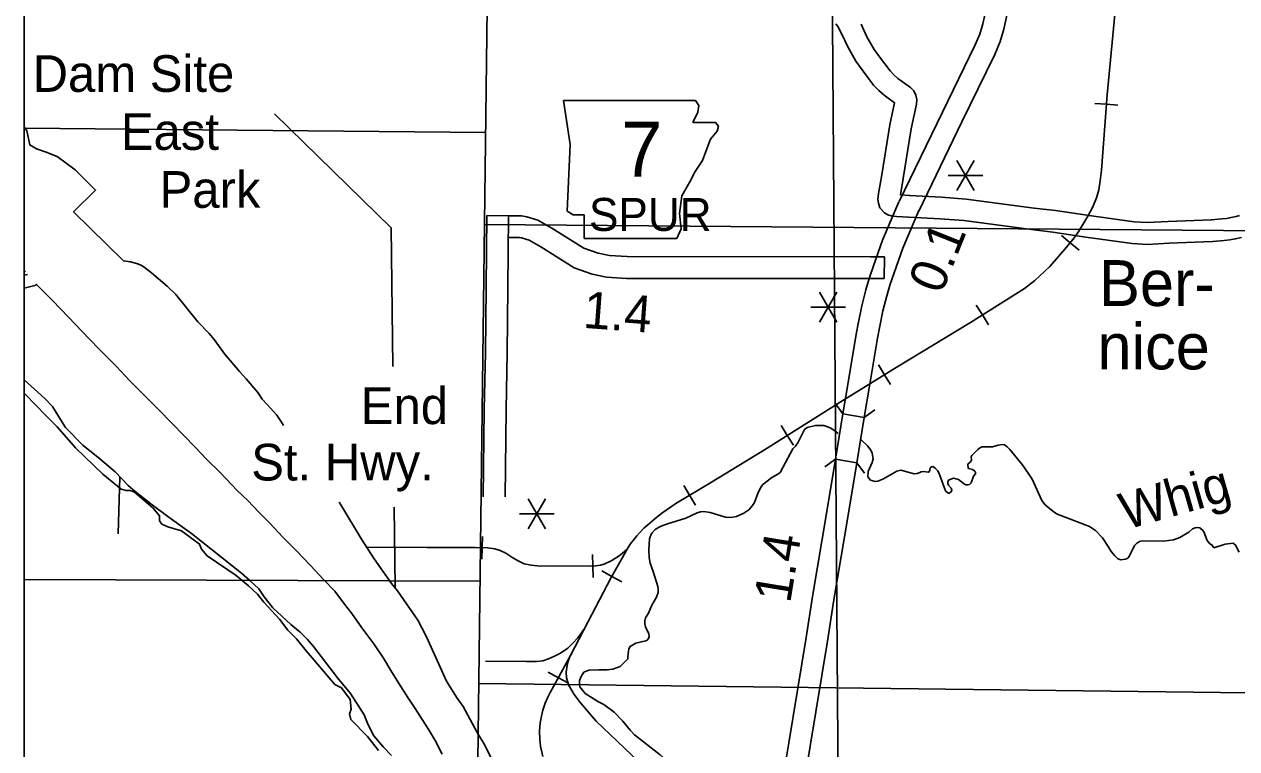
# Model space of a CAD drawing. Extents: x 1374139 to 1377472, y 1168351 to 1170484.
# Drawn here: x 1375090 to 1375369.3, y 1168970.5 to 1169137.4 of the extents above; entities that cross this region are included whole.
import ezdxf

# ---------------------------------------------------------------- set-up
doc = ezdxf.new("R2010")
doc.units = 0
doc.layers.add('26', color=7, linetype='Continuous')
doc.layers.add('Default', color=7, linetype='Continuous')

msp = doc.modelspace()

# ---------------------------------------------------------------- linework, layer by layer
at = {"layer": '26'}
msp.add_lwpolyline([(1375090, 1169579.43), (1376597.43, 1169579.43), (1376597.43, 1168653.79), (1375090, 1168653.79)], close=True, dxfattribs=at)
at = {"layer": 'Default'}
for p, q in [((1375214.22, 1169119.87), (1375215.75, 1169109.72)), ((1375245.35, 1169118.68), (1375244.65, 1169119.85)), ((1375245.18, 1169117.16), (1375245.35, 1169118.68)), ((1375339.26, 1169118.97), (1375336.63, 1169119.18)), ((1375339.26, 1169118.97), (1375341.89, 1169118.77)), ((1375244, 1169114.79), (1375245.18, 1169117.16)), ((1375249.24, 1169114.79), (1375244, 1169114.79)), ((1375248.06, 1169110.9), (1375249.58, 1169112.76)), ((1375249.92, 1169113.95), (1375249.24, 1169114.79)), ((1375249.58, 1169112.76), (1375249.92, 1169113.95)), ((1375215.75, 1169109.72), (1375215.07, 1169094.32)), ((1375247.21, 1169108.7), (1375248.06, 1169110.9)), ((1375246.2, 1169105.99), (1375247.21, 1169108.7)), ((1375244.51, 1169103.46), (1375246.2, 1169105.99)), ((1375308.78, 1169106.05), (1375304.78, 1169099.12)), ((1375304.78, 1169106.05), (1375308.78, 1169099.12)), ((1375243.32, 1169101.09), (1375244.51, 1169103.46)), ((1375302.78, 1169102.59), (1375310.78, 1169102.59)), ((1375241.46, 1169097.87), (1375243.32, 1169101.09)), ((1375240.95, 1169093.81), (1375241.46, 1169097.87)), ((1375201.53, 1169093.3), (1375196.53, 1169093.34)), ((1375215.07, 1169094.32), (1375216.42, 1169093.48)), ((1375216.42, 1169093.48), (1375218.96, 1169093.48)), ((1375218.96, 1169093.48), (1375218.96, 1169088.06)), ((1375241.29, 1169090.26), (1375240.95, 1169093.81)), ((1375196.04, 1169091.26), (1375468.4, 1169089.05)), ((1375240.28, 1169088.06), (1375241.29, 1169090.26)), ((1375218.96, 1169088.06), (1375240.28, 1169088.06)), ((1375330.93, 1169087.07), (1375328.89, 1169088.75)), ((1375330.93, 1169087.07), (1375332.96, 1169085.39)), ((1375288.08, 1169078.81), (1375288.14, 1169083.81)), ((1375090, 1169079.6), (1375090.75, 1169079.79)), ((1375090, 1169076.62), (1375092.76, 1169077.33)), ((1375277.19, 1169075.67), (1375273.19, 1169068.74)), ((1375273.19, 1169075.67), (1375277.19, 1169068.74)), ((1375271.19, 1169072.2), (1375279.19, 1169072.2)), ((1375310.7, 1169070.43), (1375309.29, 1169072.67)), ((1375310.7, 1169070.43), (1375312.11, 1169068.2)), ((1375288.17, 1169056.67), (1375286.78, 1169058.92)), ((1375288.17, 1169056.67), (1375289.56, 1169054.43)), ((1375278.57, 1169047.65), (1375283.5, 1169046.84)), ((1375265.76, 1169042.71), (1375264.36, 1169044.95)), ((1375265.76, 1169042.71), (1375267.17, 1169040.47)), ((1375276.85, 1169037.22), (1375281.78, 1169036.4)), ((1375243.26, 1169028.9), (1375241.9, 1169031.16)), ((1375243.26, 1169028.9), (1375244.63, 1169026.64)), ((1375210.08, 1169028.08), (1375206.08, 1169021.15)), ((1375206.08, 1169028.08), (1375210.08, 1169021.15)), ((1375204.09, 1169024.61), (1375212.08, 1169024.61)), ((1375195.49, 1169016.81), (1375195.58, 1169019.44)), ((1375195.49, 1169016.81), (1375195.41, 1169014.17)), ((1375220.97, 1169012.62), (1375220.92, 1169015.26)), ((1375220.97, 1169012.62), (1375221.02, 1169009.98)), ((1375225.37, 1169010.2), (1375223.06, 1169011.47)), ((1375225.37, 1169010.2), (1375227.68, 1169008.93)), ((1375213.03, 1168986.87), (1375210.71, 1168988.13)), ((1375213.03, 1168986.87), (1375215.35, 1168985.6))]:
    msp.add_line(p, q, dxfattribs=at)
for points in [[(1375192.44, 1168800.51), (1375199.95, 1169407.44)], [(1375274.18, 1169407.24), (1375277.97, 1168899.53)], [(1375303.96, 1169217.35), (1375303.54, 1169182.85), (1375303.59, 1169180.48), (1375303.86, 1169177.75), (1375304.21, 1169175.41), (1375305.24, 1169170.15), (1375307.93, 1169160.85), (1375310.54, 1169151.94), (1375311.12, 1169149.35), (1375311.5, 1169147.19), (1375311.7, 1169144.93), (1375311.72, 1169143.13), (1375311.53, 1169140.89), (1375310.82, 1169137.5), (1375310.09, 1169135.1), (1375308.99, 1169132.51), (1375301.47, 1169117.13), (1375291.53, 1169096.56)], [(1375296.03, 1169094.38), (1375305.97, 1169114.94), (1375313.53, 1169130.43), (1375314.8, 1169133.39), (1375315.66, 1169136.26), (1375316.49, 1169140.16), (1375316.72, 1169142.95), (1375316.69, 1169145.17), (1375316.47, 1169147.85), (1375316.02, 1169150.33), (1375315.39, 1169153.19), (1375312.73, 1169162.25), (1375310.11, 1169171.32), (1375309.14, 1169176.26), (1375308.83, 1169178.37), (1375308.59, 1169180.78), (1375308.54, 1169182.88), (1375308.96, 1169217.29)], [(1375334.98, 1169093.2), (1375336.12, 1169095.31), (1375337.01, 1169097.38), (1375337.54, 1169099.27), (1375337.85, 1169101.33), (1375338.1, 1169103.79), (1375339.43, 1169121.14), (1375341.48, 1169142.85)], [(1375334.98, 1169093.2), (1375336.12, 1169095.31), (1375337.01, 1169097.38), (1375337.54, 1169099.27), (1375337.85, 1169101.33), (1375338.1, 1169103.79), (1375339.43, 1169121.14), (1375341.48, 1169142.85)], [(1375278.25, 1169135.19), (1375277.45, 1169136.8), (1375276.96, 1169137.49)], [(1375293.65, 1169092.97), (1375290.91, 1169093.12), (1375289.71, 1169093.24), (1375288.88, 1169093.53), (1375288.11, 1169093.97), (1375287.06, 1169095.08), (1375286.73, 1169096.18), (1375286.62, 1169097.05), (1375286.78, 1169098.38), (1375287.5, 1169102.7), (1375289.38, 1169114.23), (1375290.47, 1169119.3), (1375288.04, 1169121.03), (1375286.81, 1169122.17), (1375285.65, 1169123.39), (1375283.2, 1169126.58), (1375281.52, 1169128.87), (1375279.67, 1169132.23), (1375278.24, 1169135.23)], [(1375282.75, 1169137.38), (1375284.11, 1169134.52), (1375285.74, 1169131.57), (1375287.2, 1169129.58), (1375289.45, 1169126.65), (1375290.33, 1169125.73), (1375291.21, 1169124.91), (1375294.13, 1169122.83), (1375294.9, 1169122.04), (1375295.38, 1169121.07), (1375295.56, 1169120.04), (1375295.52, 1169118.99), (1375294.29, 1169113.3), (1375292.43, 1169101.89), (1375291.8, 1169098.08), (1375293.91, 1169097.97)], [(1375214.22, 1169119.87), (1375244.65, 1169119.85)], [(1375174.89, 1169058.57), (1375174.55, 1169090.53), (1375147.64, 1169116.77)], [(1375090, 1169113.78), (1375090.58, 1169112.87), (1375091.3, 1169109.62), (1375092.82, 1169108.73), (1375095.08, 1169107.96), (1375097.62, 1169106.94), (1375101.76, 1169103.88), (1375106.45, 1169099.21), (1375101.35, 1169094.2), (1375112.84, 1169082.91)], [(1375196.3, 1169112.49), (1375090, 1169113.47)], [(1375291.48, 1169096.46), (1375287.72, 1169087.69), (1375285.61, 1169081.75), (1375284.71, 1169079.05), (1375283.88, 1169076.19), (1375282.93, 1169072.55), (1375282.14, 1169068.81), (1375281.62, 1169065.99), (1375279.83, 1169055.32), (1375278.57, 1169047.65)], [(1375363.49, 1169092.36), (1375353.45, 1169091.94), (1375348.62, 1169091.7), (1375345.68, 1169091.86), (1375335.27, 1169093.31), (1375327.57, 1169094.48), (1375322.64, 1169095.06), (1375306.97, 1169097.14), (1375301.28, 1169097.57), (1375293.92, 1169097.97)], [(1375196.53, 1169093.34), (1375196.41, 1169076.76), (1375196.23, 1169061.77), (1375195.97, 1169048.75), (1375195.74, 1169028.58)], [(1375200.74, 1169028.52), (1375200.97, 1169048.67), (1375201.23, 1169061.69), (1375201.41, 1169076.71), (1375201.53, 1169093.3)], [(1375288.14, 1169083.81), (1375284.96, 1169083.84), (1375228.88, 1169083.87), (1375224.78, 1169084.14), (1375222.17, 1169084.64), (1375218.88, 1169085.83), (1375211.52, 1169090.43), (1375208.28, 1169092.25), (1375205.75, 1169093.06), (1375204.53, 1169093.28), (1375201.53, 1169093.3)], [(1375209.48, 1168968.72), (1375208.94, 1168971.09), (1375208.74, 1168972.67), (1375208.69, 1168974.58), (1375208.87, 1168976.47), (1375209.12, 1168978), (1375209.46, 1168979.4), (1375209.76, 1168980.33), (1375210.02, 1168981.05), (1375210.54, 1168982.27), (1375211.15, 1168983.49), (1375211.94, 1168984.86), (1375215.83, 1168992.02), (1375219.79, 1168999.68), (1375225.22, 1169009.93), (1375228.46, 1169015.82), (1375229.12, 1169016.91), (1375229.6, 1169017.64), (1375230.58, 1169018.86), (1375231.13, 1169019.57), (1375231.81, 1169020.33), (1375232.75, 1169021.32), (1375233.64, 1169022.07), (1375235.22, 1169023.45), (1375236.86, 1169024.76), (1375240.08, 1169026.99), (1375248.28, 1169031.92), (1375260.48, 1169039.4), (1375277.9, 1169050.32), (1375290.83, 1169058.32), (1375307.98, 1169068.73), (1375320.37, 1169076.52), (1375322.8, 1169078.41), (1375326.22, 1169081.57), (1375329.71, 1169085.6), (1375331.52, 1169087.79), (1375332.05, 1169088.5), (1375332.89, 1169089.74), (1375334.98, 1169093.2)], [(1375209.48, 1168968.72), (1375208.94, 1168971.09), (1375208.74, 1168972.67), (1375208.69, 1168974.58), (1375208.87, 1168976.47), (1375209.12, 1168978), (1375209.46, 1168979.4), (1375209.76, 1168980.33), (1375210.02, 1168981.05), (1375210.54, 1168982.27), (1375211.15, 1168983.49), (1375211.94, 1168984.86), (1375215.83, 1168992.02), (1375219.79, 1168999.68), (1375225.22, 1169009.93), (1375228.46, 1169015.82), (1375229.12, 1169016.91), (1375229.6, 1169017.64), (1375230.58, 1169018.86), (1375231.13, 1169019.57), (1375231.81, 1169020.33), (1375232.75, 1169021.32), (1375233.64, 1169022.07), (1375235.22, 1169023.45), (1375236.86, 1169024.76), (1375240.08, 1169026.99), (1375248.28, 1169031.92), (1375260.48, 1169039.4), (1375277.9, 1169050.32), (1375290.83, 1169058.32), (1375307.98, 1169068.73), (1375320.37, 1169076.52), (1375322.8, 1169078.41), (1375326.22, 1169081.57), (1375329.71, 1169085.6), (1375331.52, 1169087.79), (1375332.05, 1169088.5), (1375332.89, 1169089.74), (1375334.98, 1169093.2)], [(1375283.5, 1169046.84), (1375284.76, 1169054.5), (1375286.55, 1169065.12), (1375287.05, 1169067.85), (1375287.79, 1169071.41), (1375288.69, 1169074.86), (1375289.48, 1169077.56), (1375290.34, 1169080.12), (1375292.38, 1169085.86), (1375296.08, 1169094.48)], [(1375293.65, 1169092.97), (1375300.96, 1169092.58), (1375306.45, 1169092.16), (1375322.02, 1169090.1), (1375326.9, 1169089.52), (1375334.55, 1169088.36), (1375345.2, 1169086.88), (1375348.61, 1169086.7), (1375353.68, 1169086.94), (1375363.69, 1169087.36)], [(1375369.94, 1169093.33), (1375369.15, 1169093.1), (1375367.96, 1169092.85), (1375366.95, 1169092.67), (1375365.88, 1169092.55), (1375363.39, 1169092.35)], [(1375201.5, 1169088.3), (1375204.06, 1169088.28), (1375204.53, 1169088.2), (1375206.27, 1169087.64), (1375208.97, 1169086.12), (1375216.68, 1169081.3), (1375220.84, 1169079.8), (1375224.14, 1169079.17), (1375228.72, 1169078.87), (1375284.93, 1169078.84), (1375288.08, 1169078.81)], [(1375363.79, 1169087.37), (1375366.35, 1169087.57), (1375367.66, 1169087.72), (1375368.92, 1169087.94), (1375370.37, 1169088.25)], [(1375112.84, 1169082.91), (1375114.5, 1169082.65), (1375116.13, 1169082.22), (1375117.04, 1169081.83), (1375117.6, 1169081.48), (1375119.3, 1169080.17), (1375122.93, 1169077.08), (1375124.92, 1169075.15), (1375129.99, 1169068.89), (1375132.6, 1169066.17), (1375133.72, 1169064.78), (1375136.09, 1169061.47), (1375139.55, 1169057.38), (1375141.12, 1169055.72), (1375143.83, 1169052.54), (1375144.83, 1169051.07), (1375145.93, 1169049.79), (1375148.21, 1169047.38), (1375149.22, 1169045.73), (1375149.73, 1169044.98)], [(1375090, 1169080.7), (1375090.26, 1169080.39)], [(1375129.44, 1169039.91), (1375124.07, 1169045.4), (1375120.83, 1169048.73), (1375118.19, 1169051.45), (1375114.28, 1169055.37), (1375111.28, 1169058.57), (1375107.44, 1169062.41), (1375104.92, 1169064.93), (1375100.16, 1169069.9), (1375096.48, 1169073.78), (1375092.68, 1169077.58), (1375092.65, 1169077.61)], [(1375090, 1169055.52), (1375094.77, 1169051.22), (1375096.5, 1169049.38), (1375098.33, 1169046.34), (1375099.54, 1169044.54), (1375103.46, 1169040.41), (1375107.41, 1169037.29), (1375110.91, 1169034.3), (1375113.94, 1169031.18), (1375115.52, 1169029.74), (1375119.13, 1169026.92), (1375123.39, 1169023.76), (1375128.53, 1169020.13), (1375140.05, 1169010.94), (1375141.99, 1169009.28), (1375144, 1169007.35), (1375145.27, 1169005.51), (1375147.25, 1169002.97), (1375151.41, 1168999.15), (1375153.52, 1168997.38), (1375155.24, 1168995.65), (1375156.65, 1168994.09), (1375162.12, 1168986.88), (1375165.18, 1168983.22), (1375168.31, 1168978.3), (1375169.23, 1168976.03), (1375170.55, 1168973.52), (1375172.77, 1168970.85), (1375174.58, 1168969)], [(1375090, 1169052.45), (1375092.94, 1169049.43), (1375094.67, 1169047.6), (1375097.6, 1169044.64), (1375101.77, 1169039.82), (1375108.1, 1169033.76), (1375112.33, 1169030.31), (1375113.45, 1169030.03), (1375114.46, 1169030.03), (1375115.39, 1169029.65), (1375119.7, 1169025.96), (1375121.14, 1169024.17), (1375121.14, 1169023.01), (1375121.72, 1169022.27), (1375123.08, 1169021.61), (1375124.36, 1169021.26), (1375126.26, 1169020.75), (1375130.37, 1169017.65), (1375130.84, 1169016.48), (1375132.16, 1169014.97), (1375138.84, 1169010.46), (1375141.69, 1169008.05), (1375143.7, 1169006.11), (1375145.17, 1169004.27), (1375148.78, 1169000.35), (1375150.73, 1168997.85), (1375152.7, 1168995.83), (1375154.94, 1168993.05), (1375156.34, 1168991.49), (1375161.51, 1168985.35), (1375163.06, 1168984.57), (1375165.08, 1168981.88), (1375165.28, 1168979.63), (1375164.89, 1168978.58), (1375165.2, 1168977.26), (1375169.04, 1168973.38), (1375171.6, 1168970.08)], [(1375278.57, 1169047.65), (1375276.82, 1169050.09)], [(1375285.94, 1169048.58), (1375283.5, 1169046.84)], [(1375278.57, 1169047.65), (1375276.85, 1169037.22)], [(1375283.5, 1169046.84), (1375281.78, 1169036.4)], [(1375277.46, 1169043.17), (1375277.05, 1169043.54), (1375275.75, 1169044.34), (1375274.89, 1169044.75), (1375274.15, 1169044.94), (1375272.23, 1169045), (1375270.32, 1169044.51), (1375269.75, 1169044.08), (1375268.16, 1169040.96), (1375267.66, 1169040.21)], [(1375186.24, 1168969.3), (1375184.64, 1168972.39), (1375183.23, 1168974.85), (1375181.65, 1168977.28), (1375180.08, 1168979.77), (1375178.37, 1168982.33), (1375176.24, 1168985.71), (1375174.44, 1168988.54), (1375172.77, 1168991.39), (1375170.54, 1168994.7), (1375167.78, 1168998.38), (1375165.49, 1169001.66), (1375163.78, 1169003.83), (1375161.52, 1169006.78), (1375158.86, 1169009.57), (1375155.98, 1169012.69), (1375152.63, 1169016.17), (1375149.65, 1169019.15), (1375146.47, 1169022.57), (1375144.01, 1169024.99), (1375141.51, 1169027.69), (1375139.06, 1169030.02), (1375135.22, 1169034.08), (1375131.94, 1169037.3), (1375129.44, 1169039.91)], [(1375267.66, 1169040.21), (1375267.07, 1169039.58), (1375266.47, 1169038.61), (1375264.09, 1169034.14), (1375263.56, 1169033.73), (1375262.21, 1169032.98), (1375260.08, 1169031.28), (1375259.71, 1169030.87), (1375259.03, 1169029.56), (1375258.18, 1169027.24), (1375257.77, 1169026.53), (1375256.87, 1169025.55), (1375255.78, 1169024.79), (1375254.08, 1169024.02), (1375253.2, 1169023.83), (1375252.4, 1169023.81), (1375251.56, 1169023.9), (1375248.01, 1169024.94), (1375246.57, 1169025.13), (1375245.73, 1169025.08), (1375244.98, 1169024.84), (1375242.42, 1169023.62), (1375238.19, 1169022.36), (1375236.68, 1169021.79), (1375236.07, 1169021.52), (1375235.3, 1169021.01), (1375234.61, 1169020.29), (1375234.4, 1169019.95), (1375234, 1169018.84), (1375233.86, 1169016.25), (1375233.95, 1169014.55), (1375234.21, 1169013.29), (1375234.9, 1169011.36), (1375235.92, 1169007.93), (1375236.05, 1169007.23), (1375235.99, 1169006.53), (1375235.63, 1169005.46), (1375234.58, 1169003.56), (1375233.77, 1169001.74), (1375233.11, 1169000.66), (1375232.94, 1169000), (1375232.92, 1168999.26), (1375233.07, 1168998.62), (1375233.9, 1168996.97), (1375233.95, 1168996.37), (1375233.79, 1168995.94), (1375233.48, 1168995.56), (1375233.18, 1168995.41), (1375230.86, 1168994.83), (1375229.53, 1168994.11), (1375229.24, 1168993.54), (1375229.03, 1168991.77), (1375229.06, 1168991.21), (1375227.3, 1168989.5), (1375225.57, 1168988.83), (1375224.27, 1168988.7), (1375222.38, 1168988.73), (1375220.04, 1168988.61), (1375218.91, 1168988.13), (1375218.29, 1168987.14), (1375217.92, 1168986.25), (1375217.86, 1168985.26), (1375217.97, 1168984.8), (1375219.18, 1168983.22)], [(1375296.61, 1169034.31), (1375296.31, 1169034.17), (1375295.65, 1169033.95), (1375295.01, 1169033.88), (1375291.92, 1169034.71), (1375290.99, 1169034.45), (1375287.8, 1169032.65), (1375286.59, 1169032.15), (1375285.96, 1169032.08), (1375284.91, 1169032.36), (1375284.32, 1169033.14), (1375284.38, 1169034.38), (1375285.28, 1169036.44), (1375285.51, 1169037.33), (1375285.3, 1169038.6), (1375284.99, 1169039.26), (1375284.22, 1169040.33), (1375282.66, 1169041.75)], [(1375363.99, 1169016.82), (1375363.52, 1169017.49), (1375363.06, 1169017.74), (1375362.44, 1169018.49), (1375361.71, 1169020.46), (1375361.42, 1169020.9), (1375360.77, 1169021.41), (1375360.27, 1169021.5), (1375359.72, 1169021.43), (1375359.08, 1169021.16), (1375358.22, 1169020.42), (1375356.2, 1169019.16), (1375354.71, 1169018.66), (1375352.42, 1169018.34), (1375347.51, 1169018.41), (1375346.85, 1169018.26), (1375346.18, 1169017.79), (1375345.75, 1169017.34), (1375344.43, 1169014.67), (1375344.06, 1169014.32), (1375343.66, 1169014.16), (1375342.53, 1169014.02), (1375341.84, 1169014.36), (1375341.19, 1169014.93), (1375340.34, 1169015.98), (1375339.7, 1169017.07), (1375338.33, 1169019.07), (1375336.74, 1169020.77), (1375335.36, 1169021.75), (1375327.8, 1169024.66), (1375326.53, 1169025.52), (1375325.17, 1169026.7), (1375324.36, 1169027.67), (1375322.15, 1169032.64), (1375321.41, 1169033.75), (1375319.86, 1169036.03), (1375317, 1169039.41), (1375316.37, 1169040.08), (1375315.81, 1169040.49), (1375315.32, 1169040.62), (1375314.35, 1169040.47), (1375313.02, 1169040.1), (1375310.6, 1169040.04), (1375309.99, 1169039.79), (1375309.65, 1169039.48), (1375308.26, 1169038.05), (1375308.1, 1169037.75), (1375308.18, 1169036.97), (1375307.94, 1169036.61), (1375307.37, 1169036.09), (1375307.32, 1169035.85), (1375307.41, 1169035.31), (1375307.53, 1169035.11), (1375308.41, 1169034.83), (1375308.92, 1169034.48), (1375309.09, 1169034.16), (1375309.07, 1169033.84), (1375308.68, 1169033.27)], [(1375254.14, 1168940.83), (1375254.33, 1168940.99), (1375256.08, 1168942.81), (1375257.56, 1168944.59), (1375258.78, 1168946.44), (1375260.51, 1168949.44), (1375262.03, 1168952.94), (1375263.52, 1168957.46), (1375264.53, 1168962.18), (1375266.11, 1168971.92), (1375270.08, 1168996.11), (1375271.57, 1169005.6), (1375274.79, 1169024.72), (1375276.85, 1169037.22)], [(1375274.41, 1169035.47), (1375276.85, 1169037.22)], [(1375281.78, 1169036.4), (1375279.72, 1169023.9), (1375276.5, 1169004.79), (1375275.02, 1168995.32), (1375271.05, 1168971.12), (1375269.44, 1168961.26), (1375268.35, 1168956.15), (1375266.71, 1168951.16), (1375264.98, 1168947.19), (1375263.04, 1168943.81), (1375261.57, 1168941.6), (1375259.8, 1168939.47), (1375257.76, 1168937.35), (1375257.39, 1168937.03)], [(1375281.78, 1169036.4), (1375283.53, 1169033.97)], [(1375308.68, 1169033.27), (1375308.09, 1169031.78), (1375307.69, 1169031.41), (1375307.32, 1169031.28), (1375306.98, 1169031.3), (1375306.55, 1169031.49), (1375305.18, 1169032.57), (1375304.04, 1169032.83), (1375303.04, 1169032.49), (1375302.89, 1169032.35), (1375302.71, 1169031.94), (1375302.7, 1169031.64), (1375302.85, 1169031.2), (1375303.52, 1169030.51), (1375303.68, 1169030.08), (1375303.51, 1169029.67), (1375303.06, 1169029.42), (1375302.82, 1169029.42), (1375302.23, 1169029.91), (1375300.84, 1169033.68), (1375300.41, 1169034.55), (1375299.82, 1169035.18), (1375299.27, 1169035.53), (1375298.84, 1169035.4), (1375298.64, 1169035.2), (1375298.61, 1169034.7), (1375298.42, 1169034.33), (1375298.24, 1169034.25), (1375297.14, 1169034.39), (1375296.61, 1169034.31)], [(1375112.02, 1169033.16), (1375111.66, 1169020.02)], [(1375162.55, 1169027.34), (1375162.96, 1169026.69), (1375167.72, 1169018.78), (1375170.59, 1169014.3), (1375174.62, 1169008.59), (1375175.97, 1169006.87), (1375180.66, 1169000.11), (1375182.66, 1168996.27), (1375187.24, 1168986.12), (1375189.72, 1168982.21), (1375191.09, 1168980.29), (1375194.35, 1168974.25), (1375196.06, 1168971.33), (1375197.52, 1168968.37)], [(1375175.44, 1169007.63), (1375175.24, 1169026.13)], [(1375369.86, 1169015.78), (1375369.02, 1169017.44), (1375368.43, 1169017.85), (1375366.59, 1169017.68), (1375363.99, 1169016.82)], [(1375169.09, 1169016.93), (1375193.9, 1169016.86), (1375196.67, 1169016.77), (1375198.42, 1169016.58), (1375199.65, 1169016.18), (1375200.89, 1169015.57), (1375202.52, 1169014.49), (1375203.75, 1169013.78), (1375205.17, 1169013.13), (1375206.74, 1169012.8), (1375208.83, 1169012.55), (1375212.89, 1169012.64), (1375220.52, 1169012.61), (1375221.69, 1169012.63), (1375222.72, 1169012.77), (1375223.59, 1169013.02), (1375225.35, 1169013.87), (1375227, 1169014.94), (1375227.71, 1169015.48), (1375228.86, 1169016.49)], [(1375182.74, 1169016.89), (1375193.9, 1169016.86), (1375196.67, 1169016.77), (1375198.42, 1169016.58), (1375199.65, 1169016.18), (1375200.89, 1169015.57), (1375202.52, 1169014.49), (1375203.75, 1169013.78), (1375205.17, 1169013.13), (1375206.74, 1169012.8), (1375208.83, 1169012.55), (1375212.89, 1169012.64), (1375220.52, 1169012.61), (1375221.69, 1169012.63), (1375222.72, 1169012.77), (1375223.59, 1169013.02), (1375225.35, 1169013.87), (1375227, 1169014.94), (1375227.71, 1169015.48), (1375228.86, 1169016.49)], [(1375195.02, 1169009.12), (1375090, 1169009.52)], [(1375218.91, 1168997.98), (1375217.55, 1168996.11), (1375216.27, 1168994.73), (1375215.17, 1168993.66), (1375213.54, 1168992.55), (1375212.16, 1168991.83), (1375210.78, 1168991.2), (1375209.44, 1168990.76), (1375208.02, 1168990.58), (1375205.67, 1168990.58), (1375196.22, 1168990.69)], [(1375239.67, 1168959.75), (1375221.72, 1168976.91), (1375218.13, 1168981.09), (1375216.68, 1168983.02), (1375215.34, 1168985.26), (1375214.89, 1168986.89), (1375214.79, 1168988.14), (1375215.04, 1168989.68), (1375215.28, 1168990.68), (1375215.58, 1168991.56)], [(1375194.73, 1168985.54), (1375435.2, 1168982.62)], [(1375219.18, 1168983.22), (1375222.3, 1168981.33), (1375223.51, 1168980.71), (1375225.9, 1168978.91), (1375227.85, 1168976.86), (1375229.55, 1168974.78), (1375230.6, 1168973.76), (1375236.48, 1168969.15), (1375241.47, 1168964.67), (1375242.89, 1168963.23), (1375244.83, 1168960.58), (1375245.48, 1168959.29), (1375246.14, 1168957.59), (1375246.41, 1168956.03), (1375246.49, 1168950.22), (1375246.91, 1168947.88), (1375247.25, 1168946.99), (1375247.68, 1168946.29)]]:
    msp.add_lwpolyline(points, dxfattribs=at)

# ---------------------------------------------------------------- texts
for s, height, p in [('Dam Site', 8.448, (1375091.92, 1169121.82)), ('East', 8.448, (1375112.26, 1169108.46)), ('7', 12.67, (1375227.54, 1169102.32)), ('Park', 8.448, (1375121.17, 1169095.12)), ('SPUR', 7.6, (1375220.08, 1169089.79)), ('Ber-', 10.56, (1375337.56, 1169072.5)), ('nice', 10.56, (1375337.19, 1169057.9)), ('End', 8.448, (1375167.52, 1169045.3)), ('St. Hwy.', 8.448, (1375142.28, 1169032.31))]:
    msp.add_text(s, height=height, dxfattribs=at).set_placement(p)
for s, rotation, p in [('0.1', 68.1194, (1375301.26, 1169074.97)), ('1.4', 355.7674, (1375218.57, 1169067.49)), ('Whig', 15.852, (1375343.77, 1169020.92)), ('1.4', 80.7043, (1375266.41, 1169003.87))]:
    msp.add_text(s, height=8.448, rotation=rotation, dxfattribs=at).set_placement(p)

doc.saveas('drawing.dxf')
